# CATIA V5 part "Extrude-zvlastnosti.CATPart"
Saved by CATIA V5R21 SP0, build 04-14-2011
Part number: Part1
Bounding box of the stored display mesh (mm): x 0 to 20, y -63.504 to 240.807, z -32.23 to 95.459
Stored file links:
  F:\Juraj\CATIA\Tutorialy-moje\Extrude-zvlastnosti.CATPart
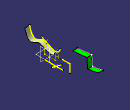
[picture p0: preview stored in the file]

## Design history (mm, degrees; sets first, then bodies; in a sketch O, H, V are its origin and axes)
Set1
  Sketch1 on yz-plane, origin (0, 0, 0), H (0, 1, 0), V (0, 0, 1)
    spline S1 through (-63.5041, 72.1821) (-26.477, 38.7761) (8.539, 45.1607) (57.244, 36.9889) (61.9578, 48.8953)
    line L1 (8.539, 45.1607) -> (-13.9208, 55.8987)
    point P1 (8.539, 45.1607)
    line L2 (-0.9841, -20.2015) -> (75.114, -20.2015)
    line L3 (68.1959, -3.8208) -> (29.6415, -32.23)
    point P7 (45.9655, -20.2015)
    point P8 (45.1597, 31.9977)
    construction line L4 (45.9655, -20.2015) -> (45.1597, 31.9977)
    construction line L5 (45.1597, 31.9977) -> (-7.0395, 31.1919)
    line L6 (68.1959, 17.1412) -> (103.0418, 17.1412)
    line L7 (103.0418, 17.1412) -> (103.0418, -16.0029)
    point P13 (8.539, 45.1607)
    point P14 (57.244, 36.9889)
    point P16 (-26.477, 38.7761)
    coincidence: P13 P1, P13 L1, L3 P7, L2 P7, S1 P8
    tangency: S1 L1, S1 L5
    fix: P16, P14, P1
    horizontal: L2 H, L6 H
    perpendicularity: L4 L5
    vertical: L7 V
  Sketch2 on yz-plane, origin (0, 0, 0), H (0, 1, 0), V (0, 0, 1)
    line L1 (134.493, 88.9602) -> (194.2944, 95.459)
    line L2 (196.9523, 55.3552) -> (240.8067, 63.0878)
    line L3 (194.2944, 95.459) -> (196.9523, 55.3552)
  Extrude1: Lim1 20, Lim2 0, Direction yz-plane, Element1 Sketch1.S1
  Extrude2: Lim1 20, Lim2 0, Element1 Sketch2
Body1 (main body)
